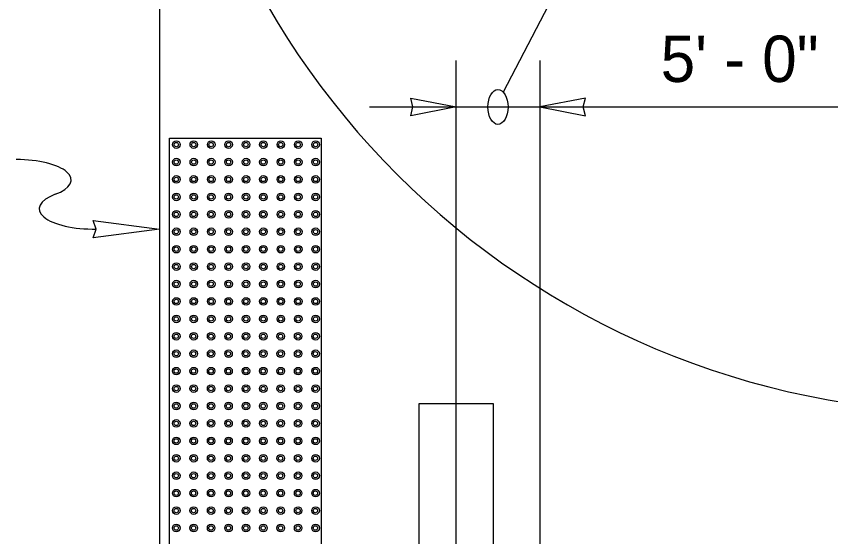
# Model space of a CAD drawing. Extents: x 99862 to 103151, y 100000 to 102076.
# Drawn here: x 100350.1 to 100630.8, y 100558.9 to 100738.5 of the extents above; entities that cross this region are included whole.
import ezdxf

# ---------------------------------------------------------------- set-up
doc = ezdxf.new("R2010")
doc.units = 0
for name, color, linetype in [('Level 15', 7, 'Continuous'), ('Level 2', 7, 'Continuous'), ('Level 20', 7, 'Continuous'), ('Level 24', 7, 'Continuous'), ('Level 5', 7, 'Continuous')]:
    doc.layers.add(name, color=color, linetype=linetype)

msp = doc.modelspace()

# ---------------------------------------------------------------- linework, layer by layer
at = {"layer": 'Level 15'}
for p, q in [((100543.71, 100762.09), (100517.95, 100712.37)), ((100501.73, 100471.7), (100501.73, 100723.22)), ((100530.54, 100723.22), (100530.54, 100476.08)), ((100471.87, 100707.22), (100501.73, 100707.22)), ((100501.73, 100707.22), (100530.54, 100707.22)), ((100530.54, 100707.22), (100670.54, 100707.22))]:
    msp.add_line(p, q, dxfattribs=at)
for points in [[(100501.77, 100707.22), (100486.05, 100704.13), (100486.78, 100707.22), (100486.05, 100710.3)], [(100530.54, 100707.22), (100546.26, 100704.13), (100545.54, 100707.22), (100546.26, 100710.3)], [(100399.44, 100665.08), (100376.62, 100662.1), (100377.67, 100665.08), (100376.61, 100668.07)]]:
    msp.add_lwpolyline(points, close=True, dxfattribs=at)
msp.add_ellipse((100516.13, 100707.22), major_axis=(0, -6), ratio=0.57735, dxfattribs=at)
for centre, start_param, end_param in [((100350.22, 100682.05), 5.497747, 7.861127), ((100376.73, 100672.11), 2.356226, 4.762505)]:
    msp.add_ellipse(centre, major_axis=(18.75, 0), ratio=0.375, start_param=start_param, end_param=end_param, dxfattribs=at)
at = {"layer": 'Level 2'}
msp.add_line((100399.47, 100881.81), (100399.47, 100041.81), dxfattribs=at)
msp.add_line((100399.47, 100881.81), (100399.47, 100041.81), dxfattribs=at)
msp.add_arc((100679.47, 100881.81), 280, 180, 270, dxfattribs=at)
msp.add_arc((100679.47, 100881.81), 280, 180, 270, dxfattribs=at)
at = {"layer": 'Level 24'}
msp.add_lwpolyline([(100488.93, 100604.86), (100514.53, 100604.86), (100514.53, 100480.3), (100488.93, 100480.3)], close=True, dxfattribs=at)
at = {"layer": 'Level 5'}
for p, q in [((100402.9, 100475.45), (100402.9, 100696.48)), ((100402.9, 100696.48), (100455.2, 100696.48)), ((100455.2, 100696.48), (100455.2, 100475.45))]:
    msp.add_line(p, q, dxfattribs=at)
for centre, major_axis in [((100405.28, 100694.24), (0, 1.31)), ((100405.25, 100694.24), (0, -0.755)), ((100411.28, 100694.24), (0, 1.31)), ((100411.25, 100694.24), (0, -0.755)), ((100417.28, 100694.24), (0, 1.31)), ((100417.25, 100694.24), (0, -0.755)), ((100423.28, 100694.24), (0, 1.31)), ((100423.25, 100694.24), (0, -0.755)), ((100429.28, 100694.24), (0, 1.31)), ((100429.25, 100694.24), (0, -0.755)), ((100435.28, 100694.24), (0, 1.31)), ((100435.25, 100694.24), (0, -0.755)), ((100441.28, 100694.24), (0, 1.31)), ((100441.25, 100694.24), (0, -0.755)), ((100447.28, 100694.24), (0, 1.31)), ((100447.25, 100694.24), (0, -0.755)), ((100453.28, 100694.24), (0, 1.31)), ((100453.25, 100694.24), (0, -0.755)), ((100405.28, 100688.22), (0, 1.31)), ((100405.25, 100688.22), (0, -0.755)), ((100411.28, 100688.22), (0, 1.31)), ((100411.25, 100688.22), (0, -0.755)), ((100417.28, 100688.22), (0, 1.31)), ((100417.25, 100688.22), (0, -0.755)), ((100423.28, 100688.22), (0, 1.31)), ((100423.25, 100688.22), (0, -0.755)), ((100429.28, 100688.22), (0, 1.31)), ((100429.25, 100688.22), (0, -0.755)), ((100435.28, 100688.22), (0, 1.31)), ((100435.25, 100688.22), (0, -0.755)), ((100441.28, 100688.22), (0, 1.31)), ((100441.25, 100688.22), (0, -0.755)), ((100447.28, 100688.22), (0, 1.31)), ((100447.25, 100688.22), (0, -0.755)), ((100453.28, 100688.22), (0, 1.31)), ((100453.25, 100688.22), (0, -0.755)), ((100405.28, 100682.21), (0, 1.31)), ((100405.25, 100682.21), (0, -0.755)), ((100411.28, 100682.21), (0, 1.31)), ((100411.25, 100682.21), (0, -0.755)), ((100417.28, 100682.21), (0, 1.31)), ((100417.25, 100682.21), (0, -0.755)), ((100423.28, 100682.21), (0, 1.31)), ((100423.25, 100682.21), (0, -0.755)), ((100429.28, 100682.21), (0, 1.31)), ((100429.25, 100682.21), (0, -0.755)), ((100435.28, 100682.21), (0, 1.31)), ((100435.25, 100682.21), (0, -0.755)), ((100441.28, 100682.21), (0, 1.31)), ((100441.25, 100682.21), (0, -0.755)), ((100447.28, 100682.21), (0, 1.31)), ((100447.25, 100682.21), (0, -0.755)), ((100453.28, 100682.21), (0, 1.31)), ((100453.25, 100682.21), (0, -0.755)), ((100405.28, 100676.19), (0, 1.31)), ((100411.28, 100676.19), (0, 1.31)), ((100417.28, 100676.19), (0, 1.31)), ((100423.28, 100676.19), (0, 1.31)), ((100429.28, 100676.19), (0, 1.31)), ((100435.28, 100676.19), (0, 1.31)), ((100441.28, 100676.19), (0, 1.31)), ((100447.28, 100676.19), (0, 1.31)), ((100453.28, 100676.19), (0, 1.31)), ((100405.25, 100676.19), (0, -0.755)), ((100411.25, 100676.19), (0, -0.755)), ((100417.25, 100676.19), (0, -0.755)), ((100423.25, 100676.19), (0, -0.755)), ((100429.25, 100676.19), (0, -0.755)), ((100435.25, 100676.19), (0, -0.755)), ((100441.25, 100676.19), (0, -0.755)), ((100447.25, 100676.19), (0, -0.755)), ((100453.25, 100676.19), (0, -0.755)), ((100405.28, 100670.18), (0, 1.31)), ((100411.28, 100670.18), (0, 1.31)), ((100417.28, 100670.18), (0, 1.31)), ((100423.28, 100670.18), (0, 1.31)), ((100429.28, 100670.18), (0, 1.31)), ((100435.28, 100670.18), (0, 1.31)), ((100441.28, 100670.18), (0, 1.31)), ((100447.28, 100670.18), (0, 1.31)), ((100453.28, 100670.18), (0, 1.31)), ((100405.25, 100670.18), (0, -0.755)), ((100411.25, 100670.18), (0, -0.755)), ((100417.25, 100670.18), (0, -0.755)), ((100423.25, 100670.18), (0, -0.755)), ((100429.25, 100670.18), (0, -0.755)), ((100435.25, 100670.18), (0, -0.755)), ((100441.25, 100670.18), (0, -0.755)), ((100447.25, 100670.18), (0, -0.755)), ((100453.25, 100670.18), (0, -0.755)), ((100405.28, 100664.17), (0, 1.31)), ((100405.25, 100664.17), (0, -0.755)), ((100411.28, 100664.17), (0, 1.31)), ((100411.25, 100664.17), (0, -0.755)), ((100417.28, 100664.17), (0, 1.31)), ((100417.25, 100664.17), (0, -0.755)), ((100423.28, 100664.17), (0, 1.31)), ((100423.25, 100664.17), (0, -0.755)), ((100429.28, 100664.17), (0, 1.31)), ((100429.25, 100664.17), (0, -0.755)), ((100435.28, 100664.17), (0, 1.31)), ((100435.25, 100664.17), (0, -0.755)), ((100441.28, 100664.17), (0, 1.31)), ((100441.25, 100664.17), (0, -0.755)), ((100447.28, 100664.17), (0, 1.31)), ((100447.25, 100664.17), (0, -0.755)), ((100453.28, 100664.17), (0, 1.31)), ((100453.25, 100664.17), (0, -0.755)), ((100405.28, 100658.15), (0, 1.31)), ((100405.25, 100658.15), (0, -0.755)), ((100411.28, 100658.15), (0, 1.31)), ((100411.25, 100658.15), (0, -0.755)), ((100417.28, 100658.15), (0, 1.31)), ((100417.25, 100658.15), (0, -0.755)), ((100423.28, 100658.15), (0, 1.31)), ((100423.25, 100658.15), (0, -0.755)), ((100429.28, 100658.15), (0, 1.31)), ((100429.25, 100658.15), (0, -0.755)), ((100435.28, 100658.15), (0, 1.31)), ((100435.25, 100658.15), (0, -0.755)), ((100441.28, 100658.15), (0, 1.31)), ((100441.25, 100658.15), (0, -0.755)), ((100447.28, 100658.15), (0, 1.31)), ((100447.25, 100658.15), (0, -0.755)), ((100453.28, 100658.15), (0, 1.31)), ((100453.25, 100658.15), (0, -0.755)), ((100405.28, 100652.14), (0, 1.31)), ((100405.25, 100652.14), (0, -0.755)), ((100411.28, 100652.14), (0, 1.31)), ((100411.25, 100652.14), (0, -0.755)), ((100417.28, 100652.14), (0, 1.31)), ((100417.25, 100652.14), (0, -0.755)), ((100423.28, 100652.14), (0, 1.31)), ((100423.25, 100652.14), (0, -0.755)), ((100429.28, 100652.14), (0, 1.31)), ((100429.25, 100652.14), (0, -0.755)), ((100435.28, 100652.14), (0, 1.31)), ((100435.25, 100652.14), (0, -0.755)), ((100441.28, 100652.14), (0, 1.31)), ((100441.25, 100652.14), (0, -0.755)), ((100447.28, 100652.14), (0, 1.31)), ((100447.25, 100652.14), (0, -0.755)), ((100453.28, 100652.14), (0, 1.31)), ((100453.25, 100652.14), (0, -0.755)), ((100405.28, 100646.12), (0, 1.31)), ((100405.25, 100646.12), (0, -0.755)), ((100411.28, 100646.12), (0, 1.31)), ((100411.25, 100646.12), (0, -0.755)), ((100417.28, 100646.12), (0, 1.31)), ((100417.25, 100646.12), (0, -0.755)), ((100423.28, 100646.12), (0, 1.31)), ((100423.25, 100646.12), (0, -0.755)), ((100429.28, 100646.12), (0, 1.31)), ((100429.25, 100646.12), (0, -0.755)), ((100435.28, 100646.12), (0, 1.31)), ((100435.25, 100646.12), (0, -0.755)), ((100441.28, 100646.12), (0, 1.31)), ((100441.25, 100646.12), (0, -0.755)), ((100447.28, 100646.12), (0, 1.31)), ((100447.25, 100646.12), (0, -0.755)), ((100453.28, 100646.12), (0, 1.31)), ((100453.25, 100646.12), (0, -0.755)), ((100405.28, 100640.11), (0, 1.31)), ((100405.25, 100640.11), (0, -0.755)), ((100411.28, 100640.11), (0, 1.31)), ((100411.25, 100640.11), (0, -0.755)), ((100417.28, 100640.11), (0, 1.31)), ((100417.25, 100640.11), (0, -0.755)), ((100423.28, 100640.11), (0, 1.31)), ((100423.25, 100640.11), (0, -0.755)), ((100429.28, 100640.11), (0, 1.31)), ((100429.25, 100640.11), (0, -0.755)), ((100435.28, 100640.11), (0, 1.31)), ((100435.25, 100640.11), (0, -0.755)), ((100441.28, 100640.11), (0, 1.31)), ((100441.25, 100640.11), (0, -0.755)), ((100447.28, 100640.11), (0, 1.31)), ((100447.25, 100640.11), (0, -0.755)), ((100453.28, 100640.11), (0, 1.31)), ((100453.25, 100640.11), (0, -0.755)), ((100405.28, 100634.1), (0, 1.31)), ((100411.28, 100634.1), (0, 1.31)), ((100417.28, 100634.1), (0, 1.31)), ((100423.28, 100634.1), (0, 1.31)), ((100429.28, 100634.1), (0, 1.31)), ((100435.28, 100634.1), (0, 1.31)), ((100441.28, 100634.1), (0, 1.31)), ((100447.28, 100634.1), (0, 1.31)), ((100453.28, 100634.1), (0, 1.31)), ((100405.25, 100634.1), (0, -0.755)), ((100411.25, 100634.1), (0, -0.755)), ((100417.25, 100634.1), (0, -0.755)), ((100423.25, 100634.1), (0, -0.755)), ((100429.25, 100634.1), (0, -0.755)), ((100435.25, 100634.1), (0, -0.755)), ((100441.25, 100634.1), (0, -0.755)), ((100447.25, 100634.1), (0, -0.755)), ((100453.25, 100634.1), (0, -0.755)), ((100405.25, 100628.1), (0, 1.31)), ((100411.25, 100628.1), (0, 1.31)), ((100417.25, 100628.1), (0, 1.31)), ((100423.25, 100628.1), (0, 1.31)), ((100429.25, 100628.1), (0, 1.31)), ((100435.25, 100628.1), (0, 1.31)), ((100441.25, 100628.1), (0, 1.31)), ((100447.25, 100628.1), (0, 1.31)), ((100453.25, 100628.1), (0, 1.31)), ((100405.21, 100628.1), (0, -0.755)), ((100411.21, 100628.1), (0, -0.755)), ((100417.21, 100628.1), (0, -0.755)), ((100423.21, 100628.1), (0, -0.755)), ((100429.21, 100628.1), (0, -0.755)), ((100435.21, 100628.1), (0, -0.755)), ((100441.21, 100628.1), (0, -0.755)), ((100447.21, 100628.1), (0, -0.755)), ((100453.21, 100628.1), (0, -0.755)), ((100405.25, 100622.08), (0, 1.31)), ((100405.21, 100622.08), (0, -0.755)), ((100411.25, 100622.08), (0, 1.31)), ((100411.21, 100622.08), (0, -0.755)), ((100417.25, 100622.08), (0, 1.31)), ((100417.21, 100622.08), (0, -0.755)), ((100423.25, 100622.08), (0, 1.31)), ((100423.21, 100622.08), (0, -0.755)), ((100429.25, 100622.08), (0, 1.31)), ((100429.21, 100622.08), (0, -0.755)), ((100435.25, 100622.08), (0, 1.31)), ((100435.21, 100622.08), (0, -0.755)), ((100441.25, 100622.08), (0, 1.31)), ((100441.21, 100622.08), (0, -0.755)), ((100447.25, 100622.08), (0, 1.31)), ((100447.21, 100622.08), (0, -0.755)), ((100453.25, 100622.08), (0, 1.31)), ((100453.21, 100622.08), (0, -0.755)), ((100405.25, 100616.07), (0, 1.31)), ((100405.21, 100616.07), (0, -0.755)), ((100411.25, 100616.07), (0, 1.31)), ((100411.21, 100616.07), (0, -0.755)), ((100417.25, 100616.07), (0, 1.31)), ((100417.21, 100616.07), (0, -0.755)), ((100423.25, 100616.07), (0, 1.31)), ((100423.21, 100616.07), (0, -0.755)), ((100429.25, 100616.07), (0, 1.31)), ((100429.21, 100616.07), (0, -0.755)), ((100435.25, 100616.07), (0, 1.31)), ((100435.21, 100616.07), (0, -0.755)), ((100441.25, 100616.07), (0, 1.31)), ((100441.21, 100616.07), (0, -0.755)), ((100447.25, 100616.07), (0, 1.31)), ((100447.21, 100616.07), (0, -0.755)), ((100453.25, 100616.07), (0, 1.31)), ((100453.21, 100616.07), (0, -0.755)), ((100405.25, 100610.05), (0, 1.31)), ((100405.21, 100610.05), (0, -0.755)), ((100411.25, 100610.05), (0, 1.31)), ((100411.21, 100610.05), (0, -0.755)), ((100417.25, 100610.05), (0, 1.31)), ((100417.21, 100610.05), (0, -0.755)), ((100423.25, 100610.05), (0, 1.31)), ((100423.21, 100610.05), (0, -0.755)), ((100429.25, 100610.05), (0, 1.31)), ((100429.21, 100610.05), (0, -0.755)), ((100435.25, 100610.05), (0, 1.31)), ((100435.21, 100610.05), (0, -0.755)), ((100441.25, 100610.05), (0, 1.31)), ((100441.21, 100610.05), (0, -0.755)), ((100447.25, 100610.05), (0, 1.31)), ((100447.21, 100610.05), (0, -0.755)), ((100453.25, 100610.05), (0, 1.31)), ((100453.21, 100610.05), (0, -0.755)), ((100405.25, 100604.04), (0, 1.31)), ((100405.21, 100604.04), (0, -0.755)), ((100411.25, 100604.04), (0, 1.31)), ((100411.21, 100604.04), (0, -0.755)), ((100417.25, 100604.04), (0, 1.31)), ((100417.21, 100604.04), (0, -0.755)), ((100423.25, 100604.04), (0, 1.31)), ((100423.21, 100604.04), (0, -0.755)), ((100429.25, 100604.04), (0, 1.31)), ((100429.21, 100604.04), (0, -0.755)), ((100435.25, 100604.04), (0, 1.31)), ((100435.21, 100604.04), (0, -0.755)), ((100441.25, 100604.04), (0, 1.31)), ((100441.21, 100604.04), (0, -0.755)), ((100447.25, 100604.04), (0, 1.31)), ((100447.21, 100604.04), (0, -0.755)), ((100453.25, 100604.04), (0, 1.31)), ((100453.21, 100604.04), (0, -0.755)), ((100405.25, 100598.03), (0, 1.31)), ((100405.21, 100598.03), (0, -0.755)), ((100411.25, 100598.03), (0, 1.31)), ((100411.21, 100598.03), (0, -0.755)), ((100417.25, 100598.03), (0, 1.31)), ((100417.21, 100598.03), (0, -0.755)), ((100423.25, 100598.03), (0, 1.31)), ((100423.21, 100598.03), (0, -0.755)), ((100429.25, 100598.03), (0, 1.31)), ((100429.21, 100598.03), (0, -0.755)), ((100435.25, 100598.03), (0, 1.31)), ((100435.21, 100598.03), (0, -0.755)), ((100441.25, 100598.03), (0, 1.31)), ((100441.21, 100598.03), (0, -0.755)), ((100447.25, 100598.03), (0, 1.31)), ((100447.21, 100598.03), (0, -0.755)), ((100453.25, 100598.03), (0, 1.31)), ((100453.21, 100598.03), (0, -0.755)), ((100405.25, 100592.01), (0, 1.31)), ((100405.21, 100592.01), (0, -0.755)), ((100411.25, 100592.01), (0, 1.31)), ((100411.21, 100592.01), (0, -0.755)), ((100417.25, 100592.01), (0, 1.31)), ((100417.21, 100592.01), (0, -0.755)), ((100423.25, 100592.01), (0, 1.31)), ((100423.21, 100592.01), (0, -0.755)), ((100429.25, 100592.01), (0, 1.31)), ((100429.21, 100592.01), (0, -0.755)), ((100435.25, 100592.01), (0, 1.31)), ((100435.21, 100592.01), (0, -0.755)), ((100441.25, 100592.01), (0, 1.31)), ((100441.21, 100592.01), (0, -0.755)), ((100447.25, 100592.01), (0, 1.31)), ((100447.21, 100592.01), (0, -0.755)), ((100453.25, 100592.01), (0, 1.31)), ((100453.21, 100592.01), (0, -0.755)), ((100405.25, 100586), (0, 1.31)), ((100411.25, 100586), (0, 1.31)), ((100417.25, 100586), (0, 1.31)), ((100423.25, 100586), (0, 1.31)), ((100429.25, 100586), (0, 1.31)), ((100435.25, 100586), (0, 1.31)), ((100441.25, 100586), (0, 1.31)), ((100447.25, 100586), (0, 1.31)), ((100453.25, 100586), (0, 1.31)), ((100405.21, 100586), (0, -0.755)), ((100411.21, 100586), (0, -0.755)), ((100417.21, 100586), (0, -0.755)), ((100423.21, 100586), (0, -0.755)), ((100429.21, 100586), (0, -0.755)), ((100435.21, 100586), (0, -0.755)), ((100441.21, 100586), (0, -0.755)), ((100447.21, 100586), (0, -0.755)), ((100453.21, 100586), (0, -0.755)), ((100405.25, 100579.98), (0, 1.31)), ((100405.21, 100579.98), (0, -0.755)), ((100411.25, 100579.98), (0, 1.31)), ((100411.21, 100579.98), (0, -0.755)), ((100417.25, 100579.98), (0, 1.31)), ((100417.21, 100579.98), (0, -0.755)), ((100423.25, 100579.98), (0, 1.31)), ((100423.21, 100579.98), (0, -0.755)), ((100429.25, 100579.98), (0, 1.31)), ((100429.21, 100579.98), (0, -0.755)), ((100435.25, 100579.98), (0, 1.31)), ((100435.21, 100579.98), (0, -0.755)), ((100441.25, 100579.98), (0, 1.31)), ((100441.21, 100579.98), (0, -0.755)), ((100447.25, 100579.98), (0, 1.31)), ((100447.21, 100579.98), (0, -0.755)), ((100453.25, 100579.98), (0, 1.31)), ((100453.21, 100579.98), (0, -0.755)), ((100405.25, 100573.97), (0, 1.31)), ((100405.21, 100573.97), (0, -0.755)), ((100411.25, 100573.97), (0, 1.31)), ((100411.21, 100573.97), (0, -0.755)), ((100417.25, 100573.97), (0, 1.31)), ((100417.21, 100573.97), (0, -0.755)), ((100423.25, 100573.97), (0, 1.31)), ((100423.21, 100573.97), (0, -0.755)), ((100429.25, 100573.97), (0, 1.31)), ((100429.21, 100573.97), (0, -0.755)), ((100435.25, 100573.97), (0, 1.31)), ((100435.21, 100573.97), (0, -0.755)), ((100441.25, 100573.97), (0, 1.31)), ((100441.21, 100573.97), (0, -0.755)), ((100447.25, 100573.97), (0, 1.31)), ((100447.21, 100573.97), (0, -0.755)), ((100453.25, 100573.97), (0, 1.31)), ((100453.21, 100573.97), (0, -0.755)), ((100405.25, 100567.95), (0, 1.31)), ((100405.21, 100567.95), (0, -0.755)), ((100411.25, 100567.95), (0, 1.31)), ((100411.21, 100567.95), (0, -0.755)), ((100417.25, 100567.95), (0, 1.31)), ((100417.21, 100567.95), (0, -0.755)), ((100423.25, 100567.95), (0, 1.31)), ((100423.21, 100567.95), (0, -0.755)), ((100429.25, 100567.95), (0, 1.31)), ((100429.21, 100567.95), (0, -0.755)), ((100435.25, 100567.95), (0, 1.31)), ((100435.21, 100567.95), (0, -0.755)), ((100441.25, 100567.95), (0, 1.31)), ((100441.21, 100567.95), (0, -0.755)), ((100447.25, 100567.95), (0, 1.31)), ((100447.21, 100567.95), (0, -0.755)), ((100453.25, 100567.95), (0, 1.31)), ((100453.21, 100567.95), (0, -0.755)), ((100405.25, 100561.94), (0, 1.31)), ((100405.21, 100561.94), (0, -0.755)), ((100411.25, 100561.94), (0, 1.31)), ((100411.21, 100561.94), (0, -0.755)), ((100417.25, 100561.94), (0, 1.31)), ((100417.21, 100561.94), (0, -0.755)), ((100423.25, 100561.94), (0, 1.31)), ((100423.21, 100561.94), (0, -0.755)), ((100429.25, 100561.94), (0, 1.31)), ((100429.21, 100561.94), (0, -0.755)), ((100435.25, 100561.94), (0, 1.31)), ((100435.21, 100561.94), (0, -0.755)), ((100441.25, 100561.94), (0, 1.31)), ((100441.21, 100561.94), (0, -0.755)), ((100447.25, 100561.94), (0, 1.31)), ((100447.21, 100561.94), (0, -0.755)), ((100453.25, 100561.94), (0, 1.31)), ((100453.21, 100561.94), (0, -0.755))]:
    msp.add_ellipse(centre, major_axis=major_axis, ratio=0.997648, dxfattribs=at)

# ---------------------------------------------------------------- texts
at = {"layer": 'Level 20'}
msp.add_text('5\' - 0"', height=16, dxfattribs=at).set_placement((100572.21, 100715.84))

doc.saveas('drawing.dxf')
